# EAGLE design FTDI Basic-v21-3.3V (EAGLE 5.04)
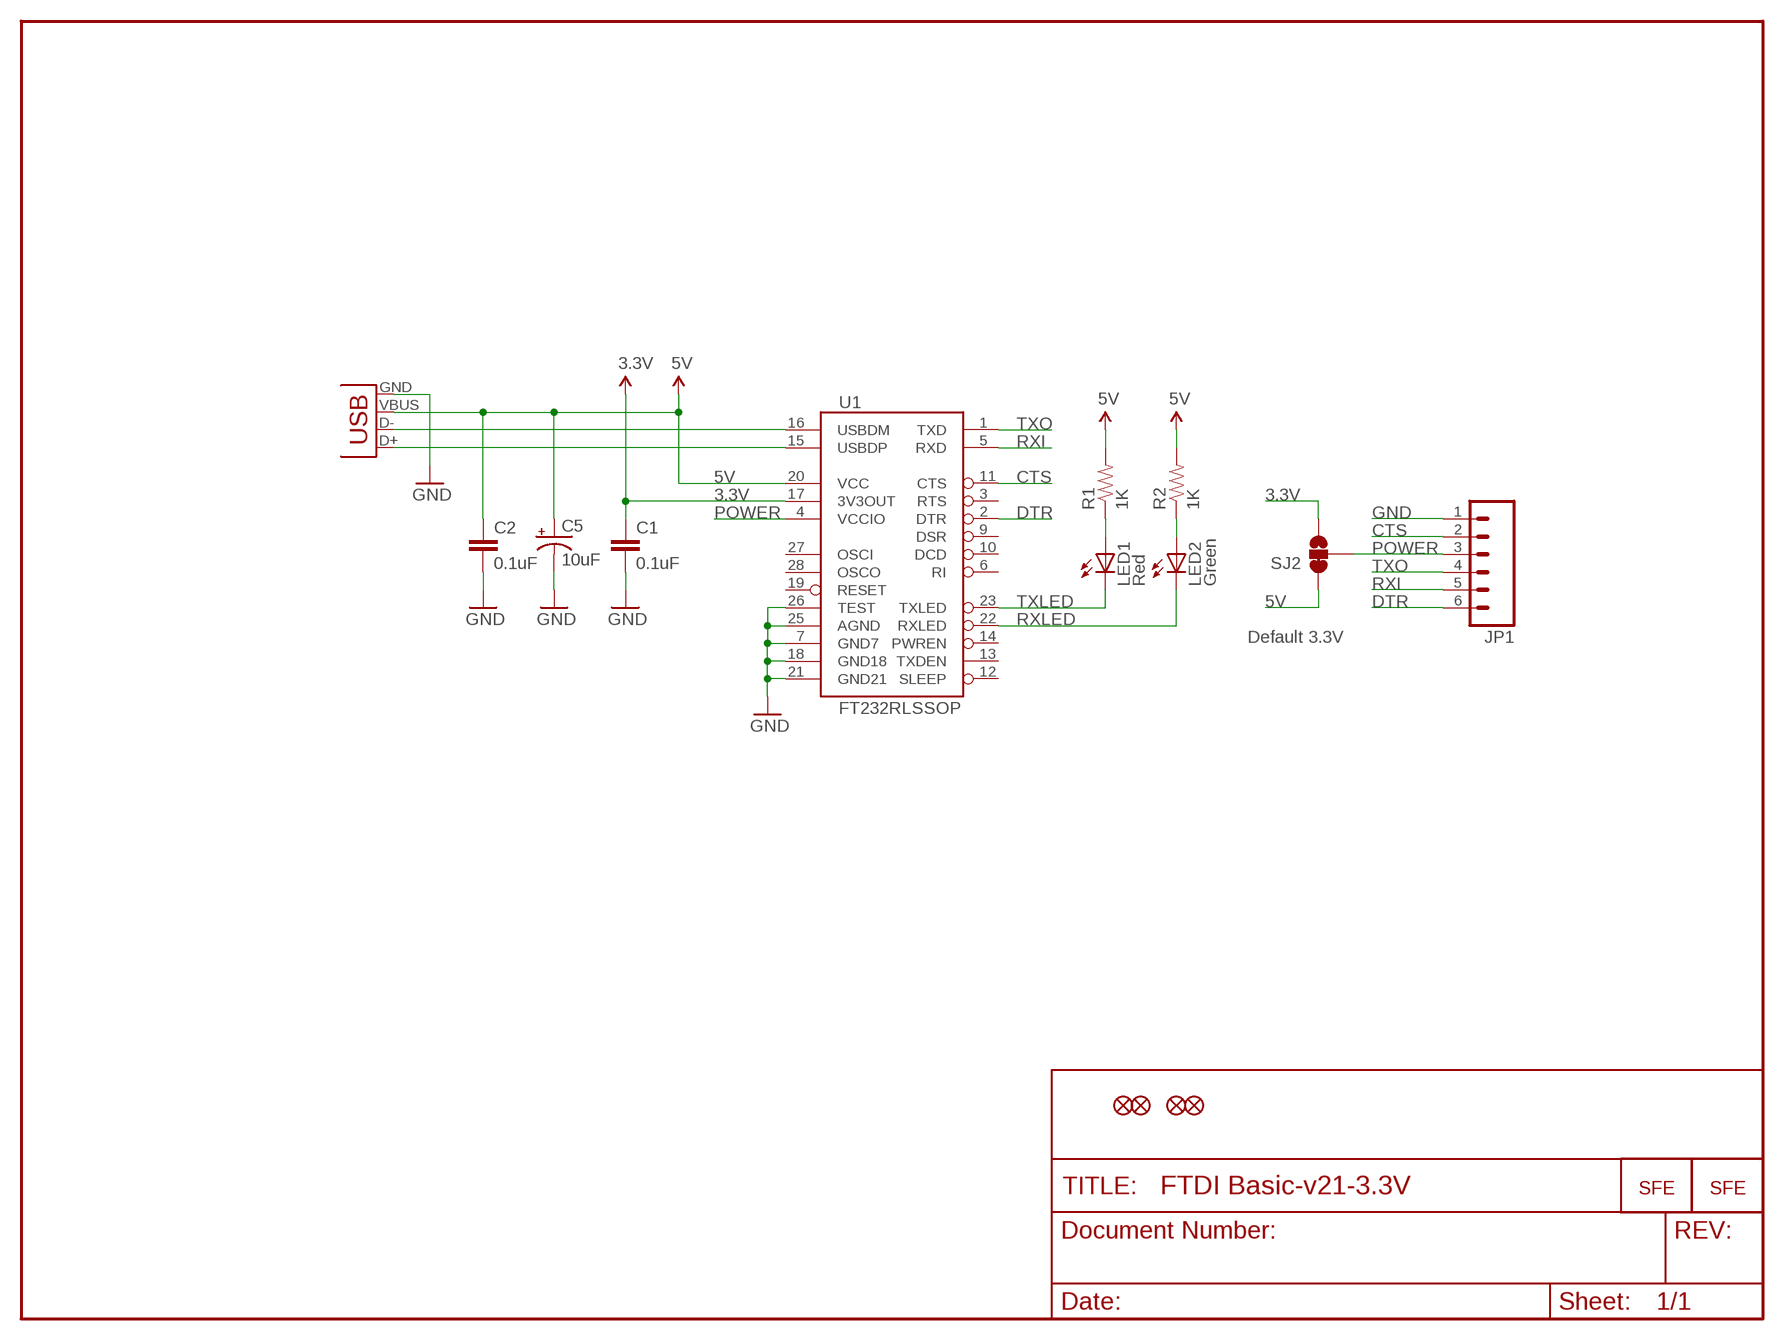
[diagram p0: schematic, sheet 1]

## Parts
C1  0.1uF  CAP0402-CAP  [0402-CAP]
C2  0.1uF  CAP0402-CAP  [0402-CAP]
C5  10uF  CAP_POL1206  [EIA3216]
JP1  M06SMD-FEMALE-V2  [1X06-SMD-FEMALE-V2]
JP2  LOGO-SFESK  [SFE-LOGO-FLAME]
JP3  FIDUCIAL1X2  [FIDUCIAL-1X2]
JP4  FIDUCIAL1X2  [FIDUCIAL-1X2]
JP5  FIDUCIAL1X2  [FIDUCIAL-1X2]
JP6  FIDUCIAL1X2  [FIDUCIAL-1X2]
LED1  Red  LED0603  [LED-0603]
LED2  Green  LED0603  [LED-0603]
R1  1K  RESISTOR0402-RES  [0402-RES]
R2  1K  RESISTOR0402-RES  [0402-RES]
SJ2  SOLDERJUMPER_2WAYS  [SJ_3]
U1  FT232RLSSOP  [SSOP28DB]
U$2  LOGO-SFENW2  [SFE-NEW-WEB]
X2  USB-SMD-NS  [USB-MINIB-NOSTOP]

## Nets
3.3V [power]: C1.1 SJ2.3 U1.17(3V3OUT)
5V: C2.1 C5.A(+) R1.2 R2.2 SJ2.1 U1.20(VCC) X2.VBUS
CTS: JP1.2 U1.11(CTS)
DTR: JP1.6 U1.2(DTR)
GND [power]: C1.2 C2.2 C5.C(-) JP1.1 U1.7(GND7) U1.18(GND18) U1.21(GND21) U1.25(AGND) U1.26(TEST) X2.GND
N$1: LED1.A R1.1
N$2: LED2.A R2.1
POWER: JP1.3 SJ2.2 U1.4(VCCIO)
RXI: JP1.5 U1.5(RXD)
RXLED: LED2.C U1.22(RXLED)
TXLED: LED1.C U1.23(TXLED)
TXO: JP1.4 U1.1(TXD)
USB_D+: U1.15(USBDP) X2.D+
USB_D-: U1.16(USBDM) X2.D-
Unconnected: U1.3(RTS) U1.6(RI) U1.9(DSR) U1.10(DCD) U1.12(SLEEP) U1.13(TXDEN) U1.14(PWREN) U1.19(RESET) U1.27(OSCI) U1.28(OSCO)

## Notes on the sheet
- Default 3.3V

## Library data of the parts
C1 C2 = SparkFun:CAP: Capacitor
C5 = SparkFun:CAP_POL: Capacitor Polarized
JP1 = SparkFun:M06: Header 6 Standard 6-pin 0.1" header. Use with straight break away headers (SKU : PRT-00116), right angle break away headers (PRT-00553), swiss pins (PRT-00743), machine pins (PRT-00117), and female headers (PRT-00115). Molex polarized connector foot print use with SKU : PRT-08094 with associated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
JP2 U$2 = SparkFun:LOGO-SFE: Spark Fun Electronics PCB Logo
JP3-JP6 = SparkFun:FIDUCIAL: Fiducial Alignment Points
LED1 LED2 = SparkFun:LED: LEDs
R1 R2 = SparkFun:RESISTOR: Resistor
SJ2 = SparkFun:SOLDERJUMPER_2WAY: Solder Jumper 2 way solder jumper
U1 = SparkFun:FT232RL: USB UART FT232RL 4th Generation USB UART (USB <-> Serial) Controller. Spark Fun Electronics SKU : COM-00650
X2 = SparkFun:USB: USB Connectors USB-B-PTH is fully proven SKU : PRT-00139 USB-miniB is fully proven SKU : PRT-00587 USB-A-PCB is untested. USB-A-H is throughly reviewed, but untested. Spark Fun Electronics SKU : PRT-00437 USB-B-SMT is throughly reviewed, but untested. Needs silkscreen touching up. USB-A-S has not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

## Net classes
0 default: width 0.203 mm
1 power: width 0.254 mm

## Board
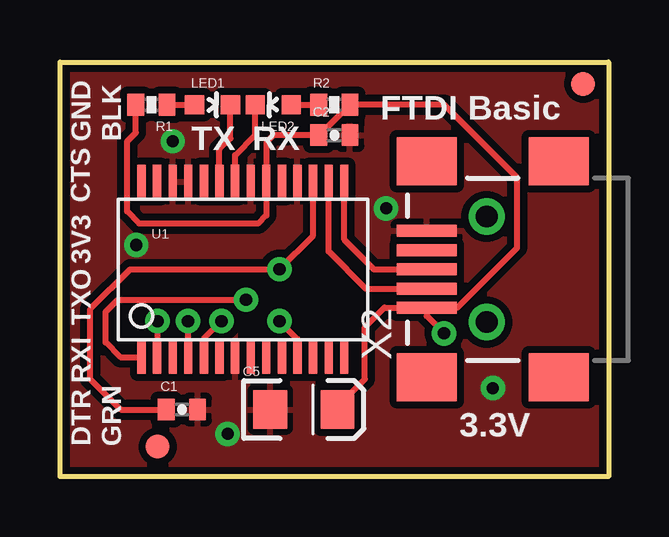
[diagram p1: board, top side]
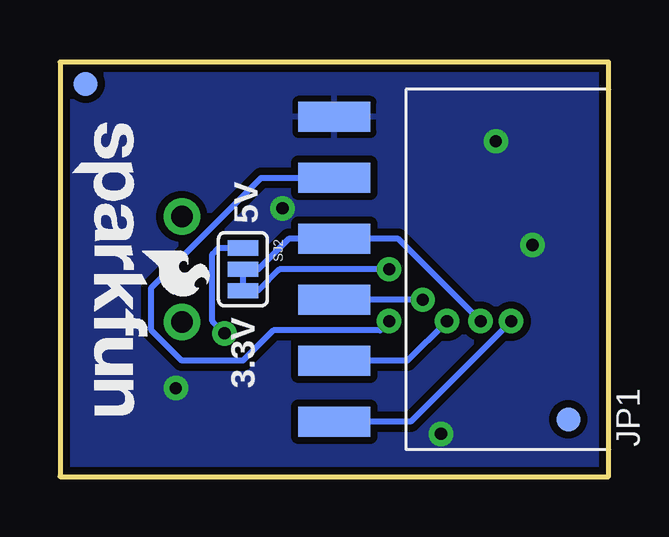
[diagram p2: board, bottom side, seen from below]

Size 22.86 x 17.27 mm. Coordinates in mm from the lower left corner, seen from the top.
Outline: 0,17.27 22.86,17.27 22.86,0 0,0 0,17.27
Copper layers (1*16): Top 0.035mm / dielectric 1.5mm / Bottom 0.035mm
Design rules "SparkFun": minimum track width 8mil, minimum drill 20mil, track to track 8mil, track to pad 8mil, pad to pad 8mil, via to via 8mil, smd to smd 8mil, copper to edge 8mil, drill to drill 8mil, minimum pad ring 12mil, minimum via ring 10mil, stop-mask expansion 4mil, vias tented up to drill 20mil, thermal gap 10mil

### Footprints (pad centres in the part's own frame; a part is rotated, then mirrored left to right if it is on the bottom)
0402-CAP = smd 0.7 x 0.9: 1 -0.65,0; 2 0.65,0
EIA3216 = smd 1.4 x 1.6: A 1.4,0; C -1.4,0
1X06-SMD-FEMALE-V2 = smd 1.25 x 3: 1 6.35,3.425; 2 3.81,3.425; 3 1.27,3.425; 4 -1.27,3.425; 5 -3.81,3.425; 6 -6.35,3.425
FIDUCIAL-1X2 = smd 1 x 1: 1 0,0
LED-0603 = smd 0.8 x 0.8: A 0,-0.75; C 0,0.75
0402-RES = smd 0.7 x 0.9: 1 -0.65,0; 2 0.65,0
SJ_3 = smd 0.635 x 1.27: 1 -0.889,0; 2 0,0; 3 0.889,0
SSOP28DB = smd 0.348 x 1.397: 1 -4.225,-3.656; 2 -3.575,-3.656; 3 -2.925,-3.656; 4 -2.275,-3.656; 5 -1.625,-3.656; 6 -0.975,-3.656; 7 -0.325,-3.656; 8 0.325,-3.656; 9 0.975,-3.656; 10 1.625,-3.656; 11 2.275,-3.656; 12 2.925,-3.656; 13 3.575,-3.656; 14 4.225,-3.656; 15 4.225,3.656; 16 3.575,3.656; 17 2.925,3.656; 18 2.275,3.656; 19 1.625,3.656; 20 0.975,3.656; 21 0.325,3.656; 22 -0.325,3.656; 23 -0.975,3.656; 24 -1.625,3.656; 25 -2.275,3.656; 26 -2.925,3.656; 27 -3.575,3.656; 28 -4.225,3.656
USB-MINIB-NOSTOP = smd 2.5 x 0.5: D+ 2.5,0; D- 2.5,0.8; GND 2.5,-1.6; ID 2.5,-0.8; VBUS 2.5,1.6 | smd 2.5 x 2: G1 -3,-4.5; G2 -3,4.5; G3 2.5,4.5; G4 2.5,-4.5 | drill 0.9 pad 0.8 round: H1 0,2.2 | drill 0.9 pad 0.787 round: H2 0,-2.2

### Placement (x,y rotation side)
C1  5.08,2.79 0 top
C2  11.43,14.22 0 top
C5  10.16,2.79 0 top
JP1  8,8.64 90 bottom
JP2  19.43,9.4 270 bottom
JP3  4.06,1.24 0 top
JP4  21.79,16.36 0 top
JP5  1.68,2.39 0 bottom
JP6  21.79,16.36 0 bottom
LED1  6.35,15.49 270 top
LED2  8.89,15.49 90 top
R1  3.81,15.49 180 top
R2  11.43,15.49 0 top
SJ2  15.24,8.64 270 bottom
U1  7.62,8.64 0 top
U$2  22.35,14.73 270 bottom
X2  17.78,8.64 180 top

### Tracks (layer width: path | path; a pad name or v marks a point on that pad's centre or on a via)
3.3V  (via drill 0.51)
  Top 0.254: C1.1 2.54,2.79 1.27,4.06 1.27,6.99 2.92,8.64 v9.14,8.64 10.54,10.04 U1.17
  Bottom 0.254: SJ2.3 14.61,7.75 13.72,8.64 v9.14,8.64
5V  (via drill 0.51)
  Top 0.254: X2.VBUS 16.56,7.04 19.05,9.53 19.05,12.45 16,15.49 R2.2 12.06,15.49 10.79,14.22 C2.1 8.89,14.22 8.6,13.93 U1.20 8.6,10.88 8.26,10.54 3.3,10.54 2.79,11.05 2.79,13.97 3.16,14.34 R1.2 | X2.VBUS 15.28,6.69 v16,5.97 | C5.A 11.56,2.92 12.7,4.06 12.7,6.22 13.51,7.04 X2.VBUS
  Bottom 0.254: SJ2.1 16.26,9.53 16.51,9.27 16.51,6.48 v16,5.97
CTS  (via drill 0.51)
  Top 0.254: U1.11 9.89,5.73 v9.14,6.48
  Bottom 0.254: JP1.2 14.48,12.45 19.05,7.87 19.05,6.1 17.78,4.83 15.24,4.83 13.97,6.1 9.53,6.1 v9.14,6.48
DTR  (via drill 0.51)
  Top 0.254: U1.2 4.06,5 v4.06,6.48
  Bottom 0.254: JP1.6 8.26,2.29 v4.06,6.48
GND  (via drill 0.51)
  other vias: 18.03,3.68 4.7,13.97 3.17,9.65 6.99,1.78 13.59,11.18
  pour Bottom (isolate 0.305): 0,-0.03 0,17.3 22.86,17.3 22.86,-0.03
  pour Top (isolate 0.305): 0,-0.03 0,17.3 22.86,17.3 22.86,-0.03
N$1
  Top 0.254: R1.1 LED1.A
N$2
  Top 0.254: LED2.A R2.1
POWER  (via drill 0.51)
  Top 0.254: v5.33,6.48 5.33,4.99 U1.4
  Bottom 0.254: 15.24,7.87 SJ2.2 14.61,8.64 13.34,9.91 JP1.3 8.76,9.91 v5.33,6.48
RXI  (via drill 0.51)
  Top 0.254: U1.5 6,5.74 v6.73,6.48
  Bottom 0.254: v6.73,6.48 8.38,4.83 JP1.5
RXLED
  Top 0.254: U1.22 7.29,13.39 8.14,14.24 LED2.C
TXLED
  Top 0.254: U1.23 6.64,13.63 7.1,14.09 LED1.C
TXO  (via drill 0.51)
  Top 0.254: U1.1 2.51,4.98 1.91,5.59 1.91,6.86 2.41,7.37 v7.75,7.37
  Bottom 0.254: v7.75,7.37 JP1.4
USB_D+
  Top 0.254: X2.D+ 13.08,8.64 11.85,9.87 U1.15
USB_D-
  Top 0.254: X2.D- 12.74,7.84 11.2,9.38 U1.16

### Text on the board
tPlace: FTDI Basic | GND | BLK | TX | RX | CTS | 3V3 | TXO | RXI | 3.3V | DTR | GRN
bPlace: 5V | 3.3V
tValues: Close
